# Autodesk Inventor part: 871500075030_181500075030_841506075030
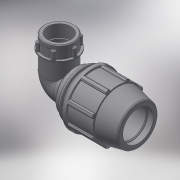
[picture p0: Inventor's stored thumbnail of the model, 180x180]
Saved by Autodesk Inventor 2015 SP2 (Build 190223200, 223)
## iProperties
Created: 2017-02
Part Number: 871500075030_181500075030_841506075030
Material: Generic
Description: PLASSON 90° ELBOW FEMALE ADAPTOR 75-3"
Document SubType Name: Modeling
Designer: KIM
Mass: 1287.77 g
Surface Area: 1760.4 cm^2
Volume: 1287.77 cm^3
Density: 1 g/cm^3
Appearance: Default
Author: KIM
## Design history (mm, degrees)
derived "87150.ipt"
feature "Solid1::87150.ipt"
tag "TaggingFeature1"
body "Solid1"
other parameters: "d2" = 75, "d4" = 16.33333, "d5" = 49, "d7" = 132, "d9" = 28, "d11" = 4.9, "d13" = 120 deg, "d14" = 97.5, "d15" = 12 deg, "d16" = 125.4, "d18" = 3.75, "d19" = 35 deg, "d20" = 17.5 deg, "d21" = 122.76, "d23" = 0, "d25" = 360 deg, "d27" = 2.64, "d33" = 1.5, "d42" = 72.52, "d43" = 3.96, "d46" = 2.25, "d51" = 196, "d68" = 9.8, "d72" = 105, "d73" = 110.4038, "d74" = 36, "d75" = 126.96437, "d76" = 84.926, "d77" = 39.6, "d79" = 33.9704, "d80" = 2.54778, "d83" = 0, "d84" = 0, "d91" = 118.8, "d93" = 137, "d94" = 84.926, "d95" = 59.4482, "d96" = 9.8, "d97" = 50 deg, "d98" = 76.4334, "d99" = 0.5, "d100" = 0.5, "d101" = 12, "d102" = 110.4038, "d103" = 30.24, "d104" = 0, "d108" = 360 deg, "d110" = 2.3658, "d111" = 8.8, "d112" = 0, "d113" = 2.45, "d114" = 2.45, "d115" = 121.638, "d_" = 75, "E_" = 132, "A_" = 196, "l_" = 137, "l_2" = 36, "A_1" = 105, "Rp_" = 84.926, "d105" = 16.56057
